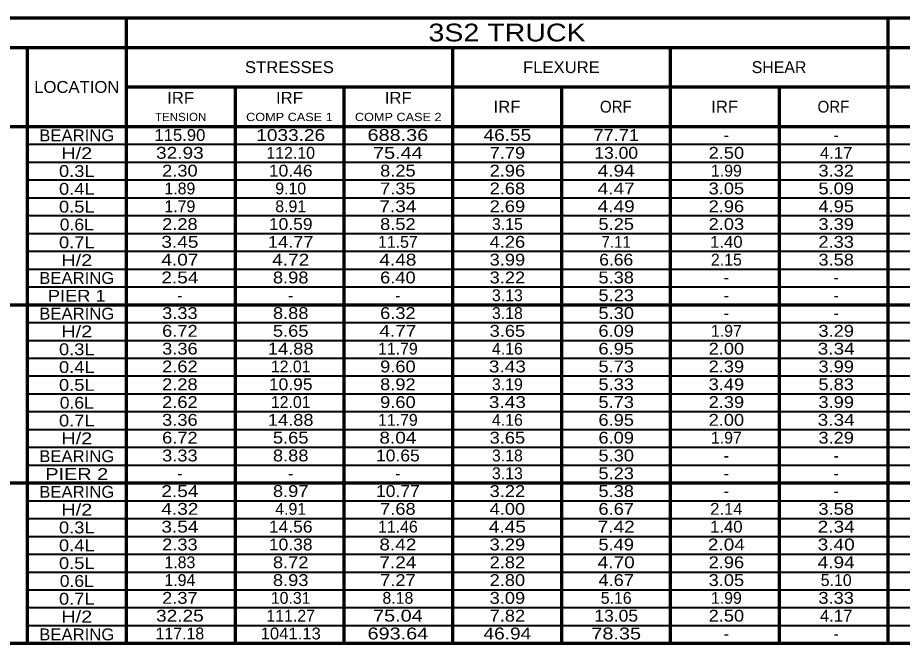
# Model space of a CAD drawing. Extents: x -1807 to -1668, y -81 to 6.
# Drawn here: x -1758.28 to -1713.57, y -66.78 to -35.15 of the extents above; entities that cross this region are included whole.
import ezdxf
from ezdxf.enums import TextEntityAlignment as Align

# ---------------------------------------------------------------- set-up
doc = ezdxf.new("R2010")
doc.units = 0
doc.header["$LTSCALE"] = 0.24
doc.layers.add('1', color=7, linetype='Continuous', lineweight=70)
doc.layers.add('5', color=7, linetype='Continuous', lineweight=40)
doc.layers.add('21', color=7, linetype='Continuous')
doc.layers.add('9', color=7, linetype='Continuous')

msp = doc.modelspace()

# ---------------------------------------------------------------- linework, layer by layer
at = {"layer": '1'}
for p, q in [((-1761.797, -35.1469), (-1675.797, -35.1469)), ((-1752.797, -35.1469), (-1752.797, -66.7771)), ((-1714.297, -35.1469), (-1714.297, -66.7771)), ((-1761.797, -36.6469), (-1675.797, -36.6469)), ((-1757.797, -36.6469), (-1757.797, -66.7771)), ((-1736.297, -36.6469), (-1736.297, -66.7771)), ((-1725.297, -36.6469), (-1725.297, -66.7771)), ((-1752.797, -38.6469), (-1675.797, -38.6469)), ((-1747.297, -38.6469), (-1747.297, -66.7771)), ((-1741.797, -38.6469), (-1741.797, -66.7771)), ((-1730.797, -38.6469), (-1730.797, -66.7771)), ((-1719.797, -38.6469), (-1719.797, -66.7771)), ((-1761.797, -40.6469), (-1675.797, -40.6469)), ((-1761.797, -49.6573), (-1675.797, -49.6573)), ((-1761.797, -58.6677), (-1675.797, -58.6677)), ((-1761.797, -66.7771), (-1675.797, -66.7771))]:
    msp.add_line(p, q, dxfattribs=at)
at = {"layer": '5'}
for p, q in [((-1757.797, -41.5479), (-1675.797, -41.5479)), ((-1757.797, -42.449), (-1675.797, -42.449)), ((-1757.797, -43.35), (-1675.797, -43.35)), ((-1757.797, -44.2511), (-1675.797, -44.2511)), ((-1757.797, -45.1521), (-1675.797, -45.1521)), ((-1757.797, -46.0532), (-1675.797, -46.0532)), ((-1757.797, -46.9542), (-1675.797, -46.9542)), ((-1757.797, -47.8552), (-1675.797, -47.8552)), ((-1757.797, -48.7563), (-1675.797, -48.7563)), ((-1757.797, -50.5583), (-1675.797, -50.5583)), ((-1757.797, -51.4594), (-1675.797, -51.4594)), ((-1757.797, -52.3604), (-1675.797, -52.3604)), ((-1757.797, -53.2615), (-1675.797, -53.2615)), ((-1757.797, -54.1625), (-1675.797, -54.1625)), ((-1757.797, -55.0636), (-1675.797, -55.0636)), ((-1757.797, -55.9646), (-1675.797, -55.9646)), ((-1757.797, -56.8657), (-1675.797, -56.8657)), ((-1757.797, -57.7667), (-1675.797, -57.7667)), ((-1757.797, -59.5688), (-1675.797, -59.5688)), ((-1757.797, -60.4698), (-1675.797, -60.4698)), ((-1757.797, -61.3708), (-1675.797, -61.3708)), ((-1757.797, -62.2719), (-1675.797, -62.2719)), ((-1757.797, -63.1729), (-1675.797, -63.1729)), ((-1757.797, -64.074), (-1675.797, -64.074)), ((-1757.797, -64.975), (-1675.797, -64.975)), ((-1757.797, -65.8761), (-1675.797, -65.8761))]:
    msp.add_line(p, q, dxfattribs=at)

# ---------------------------------------------------------------- texts
at = {"layer": '1'}
for s, width, p in [('BEARING', 1.05, (-1755.2967, -41.3974)), ('H/2', 1.25, (-1755.2968, -42.2985)), ('0.3L', 1.15, (-1755.2967, -43.1995)), ('0.4L', 1.15, (-1755.2967, -44.1006)), ('0.5L', 1.15, (-1755.2967, -45.0016)), ('0.6L', 1.1, (-1755.2968, -45.9027)), ('0.7L', 1.15, (-1755.2967, -46.8037)), ('H/2', 1.25, (-1755.2968, -47.7047)), ('BEARING', 1.05, (-1755.2967, -48.6058)), ('PIER 1', 1.15, (-1755.2968, -49.5068)), ('BEARING', 1.05, (-1755.2967, -50.4078)), ('H/2', 1.25, (-1755.2968, -51.3089)), ('0.3L', 1.15, (-1755.2967, -52.2099)), ('0.4L', 1.15, (-1755.2967, -53.111)), ('0.5L', 1.15, (-1755.2967, -54.012)), ('0.6L', 1.1, (-1755.2968, -54.9131)), ('0.7L', 1.15, (-1755.2967, -55.8141)), ('H/2', 1.25, (-1755.2968, -56.7152)), ('BEARING', 1.05, (-1755.2967, -57.6162)), ('PIER 2', 1.25, (-1755.2968, -58.5172)), ('BEARING', 1.05, (-1755.2967, -59.4183)), ('H/2', 1.25, (-1755.2968, -60.3193)), ('0.3L', 1.15, (-1755.2967, -61.2203)), ('0.4L', 1.15, (-1755.2967, -62.1214)), ('0.5L', 1.15, (-1755.2967, -63.0224)), ('0.6L', 1.1, (-1755.2968, -63.9235)), ('0.7L', 1.15, (-1755.2967, -64.8245)), ('H/2', 1.25, (-1755.2968, -65.7256)), ('BEARING', 1.05, (-1755.2967, -66.6266))]:
    msp.add_text(s, height=0.6, dxfattribs=dict(at, width=width)).set_placement(p, align=Align.CENTER)
at = {"layer": '21'}
for s, height, width, p in [('STRESSES', 0.6, 1.05, (-1744.5468, -37.9469)), ('FLEXURE', 0.6, 1.05, (-1730.7967, -37.9469)), ('LOCATION', 0.6, 1.05, (-1755.2968, -38.9469)), ('IRF', 0.6, 1.05, (-1750.0467, -39.4969)), ('IRF', 0.6, 1.05, (-1744.5467, -39.4969)), ('IRF', 0.6, 1.05, (-1739.0467, -39.4969)), ('IRF', 0.6, 1.05, (-1733.5467, -39.9469)), ('ORF', 0.6, 0.95, (-1728.0468, -39.9469)), ('IRF', 0.6, 1.05, (-1722.5467, -39.9469)), ('ORF', 0.6, 0.95, (-1717.0468, -39.9469)), ('TENSION', 0.4167, 1.05, (-1750.0468, -40.3742)), ('COMP CASE 1', 0.4167, 1.15, (-1744.5469, -40.3742)), ('COMP CASE 2', 0.4167, 1.15, (-1739.0469, -40.3742))]:
    msp.add_text(s, height=height, dxfattribs=dict(at, width=width)).set_placement(p, align=Align.CENTER)
msp.add_text('SHEAR', height=0.6, dxfattribs=at).set_placement((-1719.7968, -37.9469), align=Align.CENTER)
at = {"layer": '9'}
for s, height, width, p in [('3S2 TRUCK', 0.9, 1.2, (-1733.5465, -36.3469)), ('115.90', 0.6, 1.05, (-1750.0844, -41.3806)), ('1033.26', 0.6, 1.2, (-1744.4827, -41.3806)), ('688.36', 0.6, 1.25, (-1739.0648, -41.3806)), ('46.55', 0.6, 1.2, (-1733.5298, -41.3806)), ('77.71', 0.6, 1.15, (-1728.0284, -41.3806)), ('32.93', 0.6, 1.2, (-1750.0844, -42.2806)), ('75.44', 0.6, 1.25, (-1739.0648, -42.2806)), ('7.79', 0.6, 1.15, (-1733.5298, -42.2806)), ('13.00', 0.6, 1.1, (-1728.0285, -42.2806)), ('2.50', 0.6, 1.15, (-1722.46, -42.2806)), ('4.17', 0.6, 1.05, (-1716.9084, -42.2806)), ('2.30', 0.6, 1.15, (-1750.0844, -43.1806)), ('10.46', 0.6, 1.1, (-1744.4827, -43.1806)), ('8.25', 0.6, 1.15, (-1739.0648, -43.1806)), ('2.96', 0.6, 1.15, (-1733.5298, -43.1806)), ('4.94', 0.6, 1.2, (-1728.0284, -43.1806)), ('3.32', 0.6, 1.15, (-1716.9085, -43.1806)), ('7.35', 0.6, 1.15, (-1739.0648, -44.0806)), ('2.68', 0.6, 1.15, (-1733.5298, -44.0806)), ('4.47', 0.6, 1.2, (-1728.0285, -44.0806)), ('3.05', 0.6, 1.15, (-1722.46, -44.0806)), ('5.09', 0.6, 1.15, (-1716.9085, -44.0806)), ('7.34', 0.6, 1.2, (-1739.0648, -44.9806)), ('2.69', 0.6, 1.15, (-1733.5298, -44.9806)), ('4.49', 0.6, 1.2, (-1728.0285, -44.9806)), ('2.96', 0.6, 1.15, (-1722.46, -44.9806)), ('4.95', 0.6, 1.15, (-1716.9084, -44.9806)), ('2.28', 0.6, 1.15, (-1750.0845, -45.8806)), ('10.59', 0.6, 1.1, (-1744.4827, -45.8806)), ('8.52', 0.6, 1.15, (-1739.0648, -45.8806)), ('5.25', 0.6, 1.15, (-1728.0285, -45.8806)), ('2.03', 0.6, 1.15, (-1722.46, -45.8806)), ('3.39', 0.6, 1.15, (-1716.9085, -45.8806)), ('3.45', 0.6, 1.2, (-1750.0844, -46.7806)), ('14.77', 0.6, 1.15, (-1744.4827, -46.7806)), ('4.26', 0.6, 1.15, (-1733.5299, -46.7806)), ('7.11', 0.6, 0.95, (-1728.0284, -46.7806)), ('1.40', 0.6, 1.05, (-1722.46, -46.7806)), ('2.33', 0.6, 1.15, (-1716.9085, -46.7806)), ('4.07', 0.6, 1.2, (-1750.0844, -47.6806)), ('4.72', 0.6, 1.2, (-1744.4827, -47.6806)), ('4.48', 0.6, 1.2, (-1739.0648, -47.6806)), ('3.99', 0.6, 1.15, (-1733.5298, -47.6806)), ('6.66', 0.6, 1.1, (-1728.0284, -47.6806)), ('3.58', 0.6, 1.15, (-1716.9085, -47.6806)), ('2.54', 0.6, 1.2, (-1750.0844, -48.5806)), ('8.98', 0.6, 1.15, (-1744.4827, -48.5806)), ('6.40', 0.6, 1.15, (-1739.0648, -48.5806)), ('3.22', 0.6, 1.15, (-1733.5299, -48.5806)), ('5.38', 0.6, 1.15, (-1728.0285, -48.5806)), ('5.23', 0.6, 1.15, (-1728.0285, -49.4806)), ('3.33', 0.6, 1.15, (-1750.0845, -50.3806)), ('8.88', 0.6, 1.15, (-1744.4827, -50.3806)), ('6.32', 0.6, 1.15, (-1739.0648, -50.3806)), ('5.30', 0.6, 1.15, (-1728.0284, -50.3806)), ('6.72', 0.6, 1.15, (-1750.0844, -51.2806)), ('5.65', 0.6, 1.15, (-1744.4827, -51.2806)), ('4.77', 0.6, 1.2, (-1739.0648, -51.2806)), ('3.65', 0.6, 1.15, (-1733.5298, -51.2806)), ('6.09', 0.6, 1.15, (-1728.0284, -51.2806)), ('3.29', 0.6, 1.15, (-1716.9085, -51.2806)), ('3.36', 0.6, 1.15, (-1750.0845, -52.1806)), ('14.88', 0.6, 1.15, (-1744.4827, -52.1806)), ('6.95', 0.6, 1.15, (-1728.0285, -52.1806)), ('2.00', 0.6, 1.15, (-1722.46, -52.1806)), ('3.34', 0.6, 1.2, (-1716.9085, -52.1806)), ('2.62', 0.6, 1.15, (-1750.0844, -53.0806)), ('9.60', 0.6, 1.15, (-1739.0648, -53.0806)), ('3.43', 0.6, 1.2, (-1733.5299, -53.0806)), ('5.73', 0.6, 1.15, (-1728.0285, -53.0806)), ('2.39', 0.6, 1.15, (-1722.46, -53.0806)), ('3.99', 0.6, 1.15, (-1716.9084, -53.0806)), ('2.28', 0.6, 1.15, (-1750.0845, -53.9806)), ('10.95', 0.6, 1.1, (-1744.4827, -53.9806)), ('8.92', 0.6, 1.15, (-1739.0648, -53.9806)), ('5.33', 0.6, 1.15, (-1728.0285, -53.9806)), ('3.49', 0.6, 1.15, (-1722.46, -53.9806)), ('5.83', 0.6, 1.15, (-1716.9085, -53.9806)), ('2.62', 0.6, 1.15, (-1750.0844, -54.8806)), ('9.60', 0.6, 1.15, (-1739.0648, -54.8806)), ('3.43', 0.6, 1.2, (-1733.5299, -54.8806)), ('5.73', 0.6, 1.15, (-1728.0285, -54.8806)), ('2.39', 0.6, 1.15, (-1722.46, -54.8806)), ('3.99', 0.6, 1.15, (-1716.9084, -54.8806)), ('3.36', 0.6, 1.15, (-1750.0845, -55.7806)), ('14.88', 0.6, 1.15, (-1744.4827, -55.7806)), ('6.95', 0.6, 1.15, (-1728.0285, -55.7806)), ('2.00', 0.6, 1.15, (-1722.46, -55.7806)), ('3.34', 0.6, 1.2, (-1716.9085, -55.7806)), ('6.72', 0.6, 1.15, (-1750.0844, -56.6806)), ('5.65', 0.6, 1.15, (-1744.4827, -56.6806)), ('8.04', 0.6, 1.2, (-1739.0648, -56.6806)), ('3.65', 0.6, 1.15, (-1733.5298, -56.6806)), ('6.09', 0.6, 1.15, (-1728.0284, -56.6806)), ('3.29', 0.6, 1.15, (-1716.9085, -56.6806)), ('3.33', 0.6, 1.15, (-1750.0845, -57.5806)), ('8.88', 0.6, 1.15, (-1744.4827, -57.5806)), ('10.65', 0.6, 1.1, (-1739.0648, -57.5806)), ('5.30', 0.6, 1.15, (-1728.0284, -57.5806)), ('5.23', 0.6, 1.15, (-1728.0285, -58.4806)), ('2.54', 0.6, 1.2, (-1750.0844, -59.3806)), ('8.97', 0.6, 1.15, (-1744.4827, -59.3806)), ('10.77', 0.6, 1.1, (-1739.0648, -59.3806)), ('3.22', 0.6, 1.15, (-1733.5299, -59.3806)), ('5.38', 0.6, 1.15, (-1728.0285, -59.3806)), ('4.32', 0.6, 1.2, (-1750.0844, -60.2806)), ('7.68', 0.6, 1.15, (-1739.0647, -60.2806)), ('4.00', 0.6, 1.15, (-1733.5299, -60.2806)), ('6.67', 0.6, 1.15, (-1728.0285, -60.2806)), ('2.14', 0.6, 1.05, (-1722.46, -60.2806)), ('3.58', 0.6, 1.15, (-1716.9085, -60.2806)), ('3.54', 0.6, 1.2, (-1750.0844, -61.1806)), ('14.56', 0.6, 1.1, (-1744.4827, -61.1806)), ('4.45', 0.6, 1.2, (-1733.5298, -61.1806)), ('7.42', 0.6, 1.2, (-1728.0285, -61.1806)), ('1.40', 0.6, 1.05, (-1722.46, -61.1806)), ('2.34', 0.6, 1.2, (-1716.9085, -61.1806)), ('2.33', 0.6, 1.15, (-1750.0845, -62.0806)), ('10.38', 0.6, 1.1, (-1744.4827, -62.0806)), ('8.42', 0.6, 1.2, (-1739.0648, -62.0806)), ('3.29', 0.6, 1.15, (-1733.5299, -62.0806)), ('5.49', 0.6, 1.15, (-1728.0285, -62.0806)), ('2.04', 0.6, 1.2, (-1722.46, -62.0806)), ('3.40', 0.6, 1.2, (-1716.9084, -62.0806)), ('8.72', 0.6, 1.15, (-1744.4827, -62.9806)), ('7.24', 0.6, 1.2, (-1739.0648, -62.9806)), ('2.82', 0.6, 1.15, (-1733.5299, -62.9806)), ('4.70', 0.6, 1.2, (-1728.0284, -62.9806)), ('2.96', 0.6, 1.15, (-1722.46, -62.9806)), ('4.94', 0.6, 1.2, (-1716.9084, -62.9806)), ('8.93', 0.6, 1.15, (-1744.4827, -63.8806)), ('7.27', 0.6, 1.15, (-1739.0648, -63.8806)), ('2.80', 0.6, 1.15, (-1733.5298, -63.8806)), ('4.67', 0.6, 1.15, (-1728.0284, -63.8806)), ('3.05', 0.6, 1.15, (-1722.46, -63.8806)), ('2.37', 0.6, 1.15, (-1750.0844, -64.7806)), ('3.09', 0.6, 1.15, (-1733.5298, -64.7806)), ('3.33', 0.6, 1.15, (-1716.9085, -64.7806)), ('32.25', 0.6, 1.2, (-1750.0845, -65.6806)), ('75.04', 0.6, 1.25, (-1739.0647, -65.6806)), ('7.82', 0.6, 1.15, (-1733.5298, -65.6806)), ('13.05', 0.6, 1.1, (-1728.0284, -65.6806)), ('2.50', 0.6, 1.15, (-1722.46, -65.6806)), ('4.17', 0.6, 1.05, (-1716.9084, -65.6806)), ('1041.13', 0.6, 1.05, (-1744.4827, -66.5806)), ('693.64', 0.6, 1.25, (-1739.0648, -66.5806)), ('46.94', 0.6, 1.2, (-1733.5298, -66.5806)), ('78.35', 0.6, 1.25, (-1728.0285, -66.5806))]:
    msp.add_text(s, height=height, dxfattribs=dict(at, width=width)).set_placement(p, align=Align.CENTER)
for s, p in [('-', (-1722.46, -41.3806)), ('-', (-1716.9085, -41.3806)), ('112.10', (-1744.4827, -42.2806)), ('1.99', (-1722.46, -43.1806)), ('1.89', (-1750.0844, -44.0806)), ('9.10', (-1744.4827, -44.0806)), ('1.79', (-1750.0844, -44.9806)), ('8.91', (-1744.4826, -44.9806)), ('3.15', (-1733.5298, -45.8806)), ('11.57', (-1739.0647, -46.7806)), ('2.15', (-1722.46, -47.6806)), ('-', (-1722.46, -48.5806)), ('-', (-1716.9085, -48.5806)), ('3.13', (-1733.5298, -49.4806)), ('-', (-1750.0844, -49.4806)), ('-', (-1744.4827, -49.4806)), ('-', (-1739.0648, -49.4806)), ('-', (-1722.46, -49.4806)), ('-', (-1716.9085, -49.4806)), ('3.18', (-1733.5298, -50.3806)), ('-', (-1722.46, -50.3806)), ('-', (-1716.9085, -50.3806)), ('1.97', (-1722.46, -51.2806)), ('11.79', (-1739.0647, -52.1806)), ('4.16', (-1733.5298, -52.1806)), ('12.01', (-1744.4827, -53.0806)), ('3.19', (-1733.5298, -53.9806)), ('12.01', (-1744.4827, -54.8806)), ('11.79', (-1739.0647, -55.7806)), ('4.16', (-1733.5298, -55.7806)), ('1.97', (-1722.46, -56.6806)), ('3.18', (-1733.5298, -57.5806)), ('-', (-1722.46, -57.5806)), ('-', (-1716.9085, -57.5806)), ('3.13', (-1733.5298, -58.4806)), ('-', (-1750.0844, -58.4806)), ('-', (-1744.4827, -58.4806)), ('-', (-1739.0648, -58.4806)), ('-', (-1722.46, -58.4806)), ('-', (-1716.9085, -58.4806)), ('-', (-1722.46, -59.3806)), ('-', (-1716.9085, -59.3806)), ('4.91', (-1744.4826, -60.2806)), ('11.46', (-1739.0648, -61.1806)), ('1.83', (-1750.0844, -62.9806)), ('1.94', (-1750.0844, -63.8806)), ('5.10', (-1716.9084, -63.8806)), ('10.31', (-1744.4827, -64.7806)), ('8.18', (-1739.0648, -64.7806)), ('5.16', (-1728.0285, -64.7806)), ('1.99', (-1722.46, -64.7806)), ('111.27', (-1744.4827, -65.6806)), ('117.18', (-1750.0845, -66.5806)), ('-', (-1722.46, -66.5806)), ('-', (-1716.9085, -66.5806))]:
    msp.add_text(s, height=0.6, dxfattribs=at).set_placement(p, align=Align.CENTER)

doc.saveas('drawing.dxf')
